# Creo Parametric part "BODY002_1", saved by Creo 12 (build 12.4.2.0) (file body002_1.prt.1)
Units: Custom; MM, KILOGRAM, SECS

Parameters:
  PTC_WM_ITERATION = "0"
  PTC_WM_VERSION = "-.0"
  PTC_WM_LIFECYCLE_STATE = "In Work"
  PTC_WM_LIFECYCLE = "MO_CADDocument"
  PTC_WM_CREATED_BY = "Maximilian Roepper (Z0017RMS: MO)"
  PTC_WM_CREATED_ON = "18-Sep-26 11:36:42 AM"
  PTC_WM_MODIFIED_BY = "Maximilian Roepper (Z0017RMS: MO)"
  PTC_WM_MODIFIED_ON = "18-Sep-26 11:36:46 AM"
  PDMLINKNUMBER = "PDM000071454954"
  PTC_WM_NAME = "body002_1.prt"
  PTC_WM_NUMBER = "PDM000071454954"

Other parameters: WEIGHT, WEIGHT_FACTOR, WEIGHT_ADD, _MASS_TEMP, _DIFF_TEMP, MC_ERRORS, SUPPLIER

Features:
  1. coordinate system
  2. datum plane "PRT_YZ"
  3. datum plane "PRT_XY"
  4. datum plane "PRT_XZ"
  5. coordinate system
  6. datum axis
  7. datum axis
  8. datum axis
  9. coordinate system
  10. imported feature

Other named items: PRT, SIEMENS_MO, DRW_VIEW_ORG, PRT_X, PRT_Y, PRT_Z, CS0, ROUGH_GROB

Layers: 00_STD_CSYS-KSYS, 01_STD_PLANES-EBENEN, 02_STD_AXES-ACHSEN, 03_STD_CSYS-KSYS, 24_IMPORT_FEAT-IMPORT_KE

Surfaces: 6 plane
